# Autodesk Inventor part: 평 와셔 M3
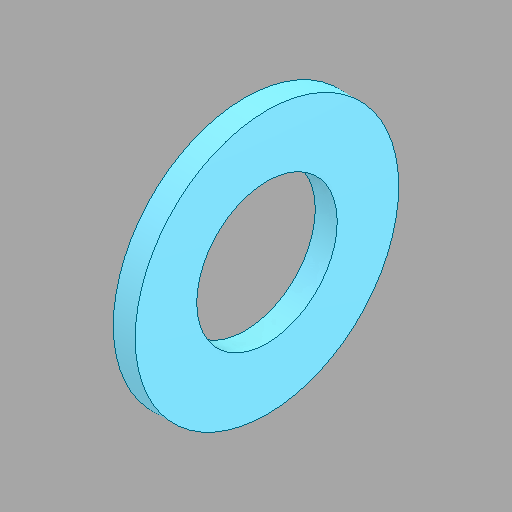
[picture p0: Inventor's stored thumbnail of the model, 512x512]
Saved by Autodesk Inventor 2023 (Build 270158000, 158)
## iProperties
Created: 2025-09
Part Number: 평 와셔 M3
Material: 강철, 연강
Description: 평면 와셔
Document SubType Name: Modeling
Designer: home
Density: 7.85 g/cm^3
Appearance: 기본값
Author: jhkim
Sending System: Autodesk Inventor 2026
Preprocessor: ST-DEVELOPER v20.1
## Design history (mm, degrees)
feature "Solid1"
node "솔리드1"
